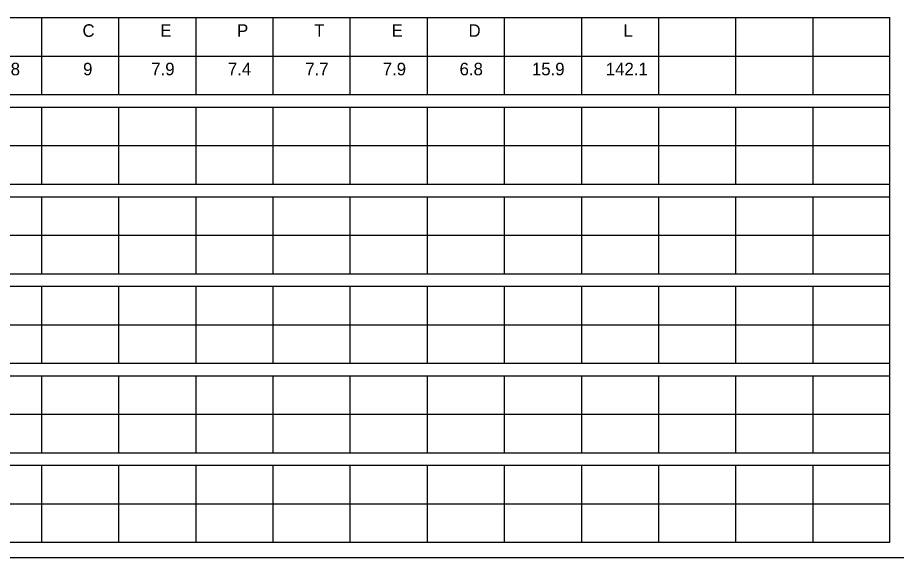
# Model space of a CAD drawing. Extents: x 17890628 to 17891459, y 17897314 to 17897992.
# Drawn here: x 17890738.41 to 17890765.84, y 17897458.39 to 17897475.25 of the extents above; entities that cross this region are included whole.
import ezdxf

# ---------------------------------------------------------------- set-up
doc = ezdxf.new("R2010")
doc.units = 0
doc.layers.add('GSDims', color=7, linetype='Continuous')
doc.layers.add('SheetLinesMisc2_dp', color=7, linetype='Continuous')

msp = doc.modelspace()

# ---------------------------------------------------------------- linework, layer by layer
at = {"layer": 'SheetLinesMisc2_dp'}
for p, q in [((17890706.449, 17897475.25), (17890765.638, 17897475.25)), ((17890739.153, 17897475.25), (17890739.153, 17897472.846)), ((17890741.56, 17897475.25), (17890741.56, 17897472.846)), ((17890743.969, 17897475.25), (17890743.969, 17897472.846)), ((17890746.376, 17897475.25), (17890746.376, 17897472.846)), ((17890748.784, 17897475.25), (17890748.784, 17897472.846)), ((17890751.191, 17897475.25), (17890751.191, 17897472.846)), ((17890753.6, 17897475.25), (17890753.6, 17897472.846)), ((17890756.007, 17897475.25), (17890756.007, 17897472.846)), ((17890758.415, 17897475.25), (17890758.415, 17897472.846)), ((17890760.822, 17897475.25), (17890760.822, 17897472.846)), ((17890763.231, 17897475.25), (17890763.231, 17897472.846)), ((17890765.638, 17897458.862), (17890765.638, 17897475.25)), ((17890706.449, 17897474.048), (17890765.638, 17897474.048)), ((17890706.449, 17897472.846), (17890765.638, 17897472.846)), ((17890706.449, 17897472.453), (17890765.638, 17897472.453)), ((17890739.153, 17897472.453), (17890739.153, 17897470.049)), ((17890741.56, 17897472.453), (17890741.56, 17897470.049)), ((17890743.969, 17897472.453), (17890743.969, 17897470.049)), ((17890746.376, 17897472.453), (17890746.376, 17897470.049)), ((17890748.784, 17897472.453), (17890748.784, 17897470.049)), ((17890751.191, 17897472.453), (17890751.191, 17897470.049)), ((17890753.6, 17897472.453), (17890753.6, 17897470.049)), ((17890756.007, 17897472.453), (17890756.007, 17897470.049)), ((17890758.415, 17897472.453), (17890758.415, 17897470.049)), ((17890760.822, 17897472.453), (17890760.822, 17897470.049)), ((17890763.231, 17897472.453), (17890763.231, 17897470.049)), ((17890706.449, 17897471.251), (17890765.638, 17897471.251)), ((17890706.449, 17897470.049), (17890765.638, 17897470.049)), ((17890706.449, 17897469.657), (17890765.638, 17897469.657)), ((17890739.153, 17897469.657), (17890739.153, 17897467.252)), ((17890741.56, 17897469.657), (17890741.56, 17897467.252)), ((17890743.969, 17897469.657), (17890743.969, 17897467.252)), ((17890746.376, 17897469.657), (17890746.376, 17897467.252)), ((17890748.784, 17897469.657), (17890748.784, 17897467.252)), ((17890751.191, 17897469.657), (17890751.191, 17897467.252)), ((17890753.6, 17897469.657), (17890753.6, 17897467.252)), ((17890756.007, 17897469.657), (17890756.007, 17897467.252)), ((17890758.415, 17897469.657), (17890758.415, 17897467.252)), ((17890760.822, 17897469.657), (17890760.822, 17897467.252)), ((17890763.231, 17897469.657), (17890763.231, 17897467.252)), ((17890706.449, 17897468.454), (17890765.638, 17897468.454)), ((17890706.449, 17897467.252), (17890765.638, 17897467.252)), ((17890706.449, 17897466.86), (17890765.638, 17897466.86)), ((17890739.153, 17897466.86), (17890739.153, 17897464.455)), ((17890741.56, 17897466.86), (17890741.56, 17897464.455)), ((17890743.969, 17897466.86), (17890743.969, 17897464.455)), ((17890746.376, 17897466.86), (17890746.376, 17897464.455)), ((17890748.784, 17897466.86), (17890748.784, 17897464.455)), ((17890751.191, 17897466.86), (17890751.191, 17897464.455)), ((17890753.6, 17897466.86), (17890753.6, 17897464.455)), ((17890756.007, 17897466.86), (17890756.007, 17897464.455)), ((17890758.415, 17897466.86), (17890758.415, 17897464.455)), ((17890760.822, 17897466.86), (17890760.822, 17897464.455)), ((17890763.231, 17897466.86), (17890763.231, 17897464.455)), ((17890706.449, 17897465.658), (17890765.638, 17897465.658)), ((17890706.449, 17897464.455), (17890765.638, 17897464.455)), ((17890706.449, 17897464.063), (17890765.638, 17897464.063)), ((17890739.153, 17897464.063), (17890739.153, 17897461.659)), ((17890741.56, 17897464.063), (17890741.56, 17897461.659)), ((17890743.969, 17897464.063), (17890743.969, 17897461.659)), ((17890746.376, 17897464.063), (17890746.376, 17897461.659)), ((17890748.784, 17897464.063), (17890748.784, 17897461.659)), ((17890751.191, 17897464.063), (17890751.191, 17897461.659)), ((17890753.6, 17897464.063), (17890753.6, 17897461.659)), ((17890756.007, 17897464.063), (17890756.007, 17897461.659)), ((17890758.415, 17897464.063), (17890758.415, 17897461.659)), ((17890760.822, 17897464.063), (17890760.822, 17897461.659)), ((17890763.231, 17897464.063), (17890763.231, 17897461.659)), ((17890706.449, 17897462.861), (17890765.638, 17897462.861)), ((17890706.449, 17897461.659), (17890765.638, 17897461.659)), ((17890706.449, 17897461.267), (17890765.638, 17897461.267)), ((17890739.153, 17897461.267), (17890739.153, 17897458.862)), ((17890741.56, 17897461.267), (17890741.56, 17897458.862)), ((17890743.969, 17897461.267), (17890743.969, 17897458.862)), ((17890746.376, 17897461.267), (17890746.376, 17897458.862)), ((17890748.784, 17897461.267), (17890748.784, 17897458.862)), ((17890751.191, 17897461.267), (17890751.191, 17897458.862)), ((17890753.6, 17897461.267), (17890753.6, 17897458.862)), ((17890756.007, 17897461.267), (17890756.007, 17897458.862)), ((17890758.415, 17897461.267), (17890758.415, 17897458.862)), ((17890760.822, 17897461.267), (17890760.822, 17897458.862)), ((17890763.231, 17897461.267), (17890763.231, 17897458.862)), ((17890706.449, 17897460.065), (17890765.638, 17897460.065)), ((17890706.449, 17897458.862), (17890765.638, 17897458.862)), ((17890705.872, 17897458.39), (17890826.223, 17897458.39))]:
    msp.add_line(p, q, dxfattribs=at)

# ---------------------------------------------------------------- texts
at = {"layer": 'GSDims'}
for s, height, p in [('C', 0.392, (17890740.434, 17897474.649)), ('E', 0.392, (17890742.861, 17897474.649)), ('P', 0.392, (17890745.26, 17897474.649)), ('T', 0.392, (17890747.669, 17897474.649)), ('E', 0.392, (17890750.086, 17897474.649)), ('D', 0.392, (17890752.485, 17897474.649)), ('L', 0.392, (17890757.321, 17897474.649)), ('8.8', 0.3921, (17890737.755, 17897473.447)), ('9', 0.392, (17890740.453, 17897473.447)), ('7.9', 0.3921, (17890742.581, 17897473.447)), ('7.4', 0.3921, (17890744.971, 17897473.447)), ('7.7', 0.3921, (17890747.389, 17897473.447)), ('7.9', 0.3921, (17890749.806, 17897473.447)), ('6.8', 0.3921, (17890752.205, 17897473.447)), ('15.9', 0.3921, (17890754.464, 17897473.447)), ('142.1', 0.3921, (17890756.77, 17897473.447))]:
    msp.add_text(s, height=height, dxfattribs=at).set_placement(p)

doc.saveas('drawing.dxf')
